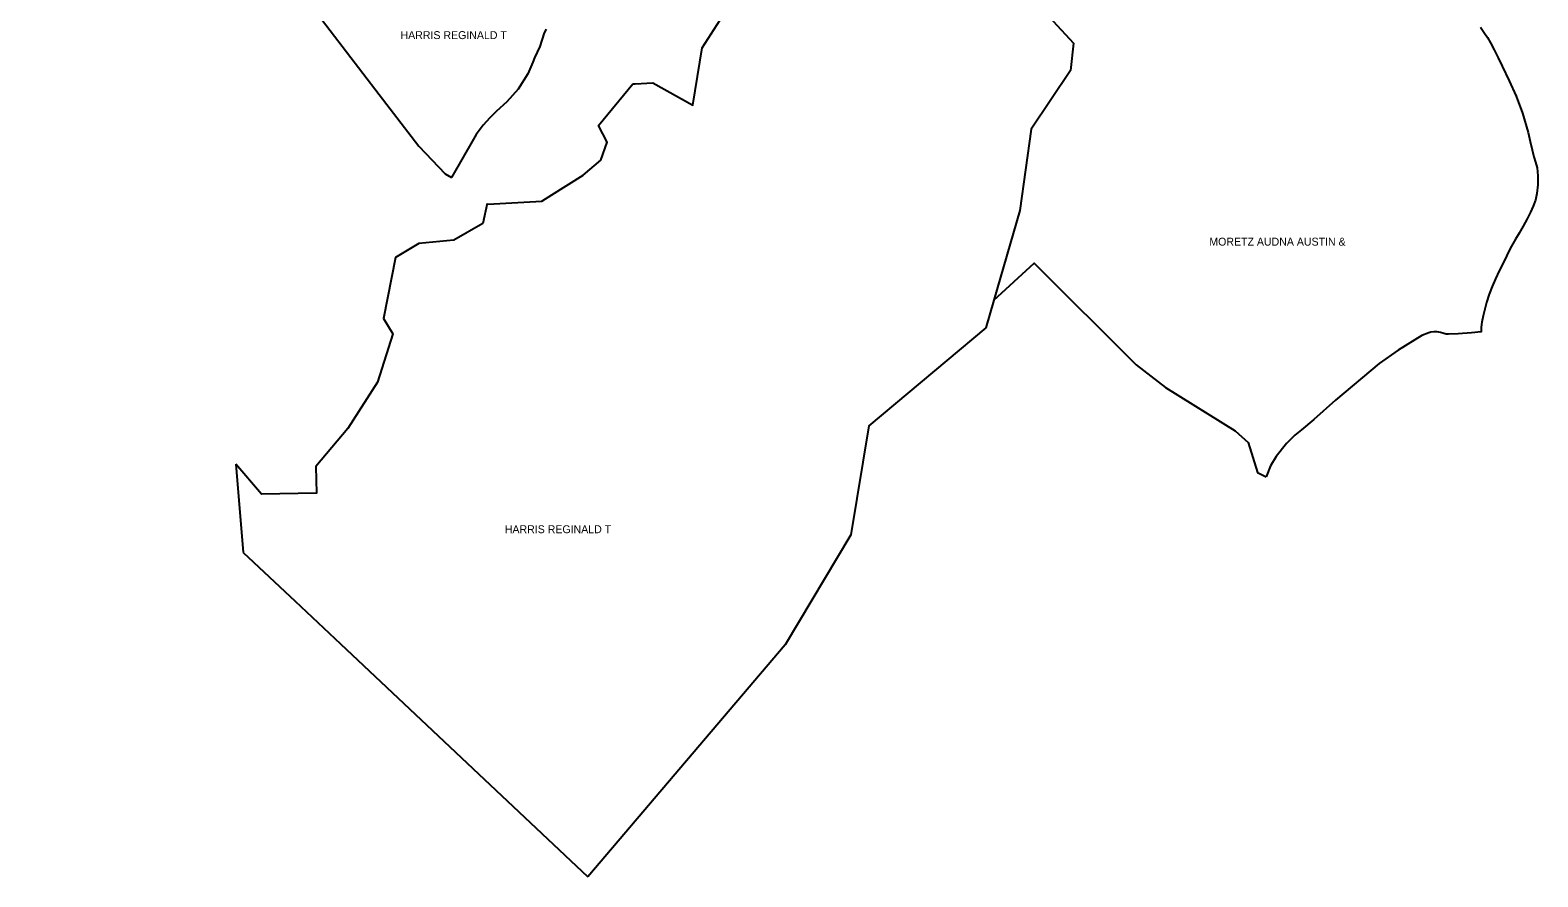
# Model space of a CAD drawing. Extents: x 1249333 to 1254314, y 856599 to 862241.
# Drawn here: x 1250485 to 1253842, y 856599 to 858486 of the extents above; entities that cross this region are included whole.
import ezdxf

# ---------------------------------------------------------------- set-up
doc = ezdxf.new("R2010")
doc.units = 0
doc.layers.add('Old_Level_12', color=7, linetype='Continuous')
doc.layers.add('Old_Level_32', color=7, linetype='Continuous')

msp = doc.modelspace()

# ---------------------------------------------------------------- linework, layer by layer
at = {"layer": 'Old_Level_12'}
for p, q in [((1251471.75, 858242.938), (1251422.875, 858157.125)), ((1251428.5, 858017.5), (1251350.25, 858010.125)), ((1252630.5, 857884.25), (1252612.75, 857822.875)), ((1250942.5, 857519.125), (1250959.25, 857321.875)), ((1250959.25, 857321.875), (1251074.875, 857213.188)), ((1251074.875, 857213.188), (1251175.75, 857118.438)), ((1251175.75, 857118.438), (1251726.875, 856599.313))]:
    msp.add_line(p, q, dxfattribs=at)
for points in [[(1250484.75, 858984.188), (1251080.125, 858580.625), (1251261.875, 858342.75), (1251350.125, 858227.063), (1251408.875, 858165.875), (1251422.875, 858157.125)], [(1253021.75, 858998.313), (1252940, 858957.438), (1252872.875, 858935), (1252805.625, 858929), (1252722.375, 858888.5), (1252691.625, 858787.813), (1252690, 858729.813), (1252706.5, 858621.438), (1252763.25, 858505.438), (1252808.5, 858456.688), (1252801.25, 858395.875), (1252713.625, 858265.5), (1252688.5, 858083.875), (1252630.5, 857884.25)], [(1251826.75, 858365.938), (1251832.375, 858366.25), (1251871.75, 858368.688), (1251960.125, 858318.688), (1251981.25, 858446.25), (1252027.75, 858519.438), (1252003.25, 858604.25), (1252000.125, 858642.625), (1252003.875, 858648.375), (1252007.375, 858654.125), (1252010.5, 858659.813), (1252012.875, 858665.438), (1252014.625, 858670.688), (1252016.5, 858676.563), (1252018.375, 858682.125), (1252019, 858683.813)], [(1251633.5, 858487.813), (1251629.125, 858479.563), (1251619.625, 858449.688), (1251608.25, 858423.813), (1251604.375, 858414.75), (1251593.125, 858388.313), (1251571.25, 858354.25), (1251546.625, 858325.688), (1251523.625, 858304.938), (1251520.5, 858302.125), (1251508.75, 858290.688), (1251493.625, 858274.125), (1251478, 858253.375), (1251471.75, 858242.938)], [(1253714.625, 858492.563), (1253723.125, 858479.375), (1253730, 858469.063), (1253737, 858457.375), (1253745, 858442.063), (1253753.625, 858424.375), (1253762.75, 858405.438), (1253778.625, 858372.875), (1253793.875, 858338.563), (1253808.125, 858300.688), (1253820.75, 858257.5), (1253825.375, 858237.875), (1253829.375, 858219.438), (1253833.125, 858203.688), (1253837.125, 858191.875), (1253840.5, 858178.875), (1253842.25, 858161.063), (1253842, 858141.063), (1253840, 858121.5), (1253836.75, 858106.75), (1253832, 858093.25), (1253825.875, 858079.875), (1253818.375, 858065.5), (1253809.375, 858049.188), (1253800.5, 858033.438), (1253792.625, 858019.875), (1253786.75, 858009.875), (1253780.75, 857999), (1253773.125, 857983.938), (1253764.75, 857966.813), (1253756.375, 857949.5), (1253748, 857931.688), (1253740.5, 857914.938), (1253734, 857897.813), (1253728, 857879.125), (1253724, 857864.063), (1253720.5, 857849.063), (1253717.875, 857835.375), (1253716.375, 857824.313), (1253715.875, 857816.688), (1253715.875, 857813.313), (1253694.625, 857811.438), (1253664.625, 857809.125), (1253643.625, 857808.375), (1253638, 857808.688), (1253630.875, 857810.375), (1253625.125, 857812.313), (1253618, 857813.75), (1253610.625, 857813.875), (1253604.25, 857813.063), (1253599.125, 857811.75), (1253584, 857805.438), (1253531.125, 857772.875), (1253488.875, 857743.188), (1253391.875, 857661.063), (1253343.5, 857618.313), (1253315.75, 857595.438), (1253301.25, 857583.563), (1253282.5, 857564.625), (1253259.875, 857535.688), (1253246.75, 857514.813), (1253237.25, 857490.75)], [(1251646.625, 858118.625), (1251716.5, 858162.688), (1251755.75, 858195.875), (1251769.625, 858236), (1251750.125, 858273.5), (1251826.75, 858365.938)], [(1251502.125, 858099.688), (1251504.125, 858098.313), (1251624.5, 858104.688), (1251646.625, 858118.625)], [(1251502.125, 858099.688), (1251492.875, 858054.688), (1251428.5, 858017.5)], [(1251350.25, 858010.125), (1251298.5, 857979.5), (1251271.75, 857843.438), (1251292.5, 857809.125), (1251258.5, 857701.5), (1251192.5, 857597.938), (1251121, 857513.5), (1251122.5, 857454.313), (1250999.75, 857452.313), (1250942.5, 857519.125)], [(1252630.5, 857884.25), (1252720.875, 857966.688), (1252948, 857739.875), (1253013.25, 857689.938), (1253168, 857593.125), (1253196.875, 857567.125), (1253217.625, 857500.313), (1253237.25, 857490.75)], [(1252612.75, 857822.875), (1252352.125, 857604.313), (1252312.5, 857361.5), (1252166.125, 857115.938), (1251726.875, 856599.313)]]:
    msp.add_lwpolyline(points, dxfattribs=at)

# ---------------------------------------------------------------- texts
at = {"layer": 'Old_Level_32'}
for s, p in [('HARRIS REGINALD T', (1251309.5, 858465.875)), ('MORETZ AUDNA AUSTIN &', (1253110.625, 858005.688)), ('HARRIS REGINALD T', (1251541.75, 857365))]:
    msp.add_text(s, height=17.61477, dxfattribs=at).set_placement(p)

doc.saveas('drawing.dxf')
